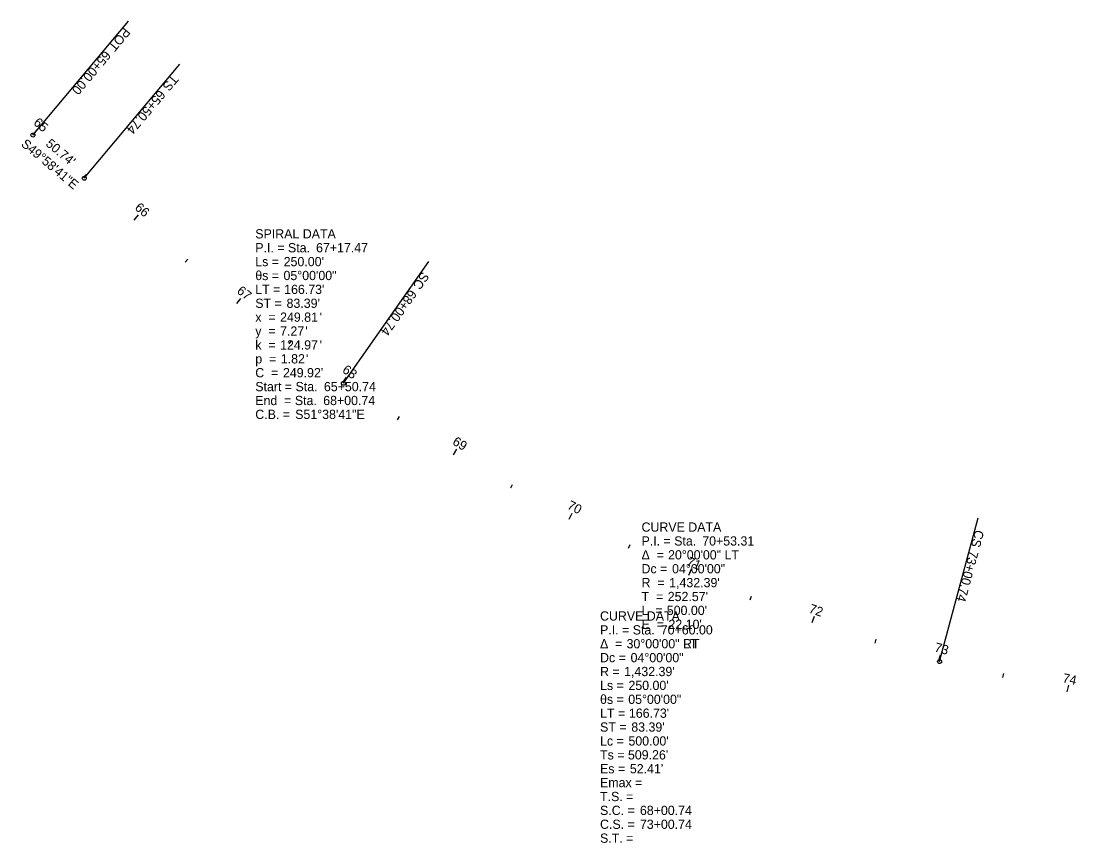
# Model space of a CAD drawing. Extents: x 1999328 to 2003366, y 252318 to 253988.
# Drawn here: x 1999328 to 2000126, y 253367 to 253988 of the extents above; entities that cross this region are included whole.
import ezdxf

# ---------------------------------------------------------------- set-up
doc = ezdxf.new("R2010")
doc.units = 0
for name, color, linetype in [('GE_P_Alignment_500_Stations', 7, 'Continuous'), ('GE_X_Alignment_100_Stations', 7, 'Continuous'), ('SC_Scratch3', 7, 'Continuous'), ('SV_X_Mon_Cells_Found', 7, 'Continuous'), ('TX_P_50', 7, 'Continuous'), ('TX_X_50', 7, 'Continuous')]:
    doc.layers.add(name, color=color, linetype=linetype)

msp = doc.modelspace()

# ---------------------------------------------------------------- linework, layer by layer
at = {"layer": 'GE_P_Alignment_500_Stations'}
for p, q in [((1999336.91, 253901.92), (1999409.26, 253988.07)), ((1999375.77, 253869.29), (1999448.11, 253955.44)), ((1999336.91, 253901.92), (1999340.13, 253905.75)), ((1999375.2, 253869.77), (1999377.13, 253872.07)), ((1999413.53, 253837.66), (1999416.73, 253841.5)), ((1999452.07, 253805.81), (1999453.97, 253808.13)), ((1999571.75, 253714.21), (1999636.31, 253806.34)), ((1999491.06, 253774.5), (1999494.15, 253778.43)), ((1999530.68, 253744.01), (1999532.48, 253746.41)), ((1999571.14, 253714.63), (1999574.01, 253718.73)), ((1999612.56, 253686.64), (1999614.2, 253689.15)), ((1999654.94, 253660.11), (1999657.52, 253664.39)), ((1999698.22, 253635.07), (1999699.67, 253637.69)), ((1999742.34, 253611.56), (1999744.62, 253616.01)), ((2000022.52, 253503.8), (2000051.68, 253612.46)), ((1999787.26, 253589.6), (1999788.53, 253592.32)), ((1999832.92, 253569.22), (1999834.87, 253573.82)), ((1999879.26, 253550.45), (1999880.33, 253553.25)), ((1999926.22, 253533.31), (1999927.85, 253538.04)), ((1999973.76, 253517.82), (1999974.64, 253520.68)), ((2000021.81, 253503.99), (2000023.11, 253508.82)), ((2000070.3, 253491.8), (2000070.98, 253494.72)), ((2000119.11, 253480.97), (2000120.13, 253485.86))]:
    msp.add_line(p, q, dxfattribs=at)
for centre in [(1999336.91, 253901.92), (1999375.77, 253869.29), (1999571.75, 253714.21), (2000022.52, 253503.8)]:
    msp.add_circle(centre, 1.5, dxfattribs=at)
at = {"layer": 'SV_X_Mon_Cells_Found'}
for p, q in [((1999336.91, 253901.92), (1999409.26, 253988.07)), ((1999375.77, 253869.29), (1999448.11, 253955.44)), ((1999336.91, 253901.92), (1999338.84, 253904.22)), ((1999571.75, 253714.21), (1999636.31, 253806.34)), ((1999742.34, 253611.56), (1999744.62, 253616.01)), ((2000022.52, 253503.8), (2000051.68, 253612.46))]:
    msp.add_line(p, q, dxfattribs=at)
for centre in [(1999336.91, 253901.92), (1999375.77, 253869.29), (1999571.75, 253714.21), (2000022.52, 253503.8)]:
    msp.add_circle(centre, 1.5, dxfattribs=at)
at = {"layer": 'TX_P_50'}
for p, q in [((1999336.91, 253901.92), (1999409.26, 253988.07)), ((1999375.77, 253869.29), (1999448.11, 253955.44)), ((1999336.91, 253901.92), (1999340.13, 253905.75)), ((1999413.53, 253837.66), (1999415.45, 253839.96)), ((1999571.75, 253714.21), (1999636.31, 253806.34)), ((1999491.06, 253774.5), (1999492.91, 253776.86)), ((1999571.14, 253714.63), (1999572.86, 253717.09)), ((1999654.94, 253660.11), (1999656.49, 253662.68)), ((1999742.34, 253611.56), (1999744.62, 253616.01)), ((2000022.52, 253503.8), (2000051.68, 253612.46)), ((1999832.92, 253569.22), (1999834.09, 253571.98)), ((1999926.22, 253533.31), (1999927.2, 253536.14)), ((2000021.81, 253503.99), (2000022.59, 253506.89)), ((2000119.11, 253480.97), (2000119.72, 253483.91))]:
    msp.add_line(p, q, dxfattribs=at)
for centre in [(1999336.91, 253901.92), (1999375.77, 253869.29), (1999571.75, 253714.21), (2000022.52, 253503.8)]:
    msp.add_circle(centre, 1.5, dxfattribs=at)

# ---------------------------------------------------------------- texts
at = {"layer": 'GE_P_Alignment_500_Stations'}
for s, rotation, p in [('POT', 229.97809, (1999405.8, 253983.77)), ('65+00.00', 229.97809, (1999391.12, 253966.29)), ('TS', 229.97809, (1999442.14, 253948.15)), ('65+50.74', 229.97809, (1999432.36, 253936.5)), ('65', 319.97809, (1999336.78, 253910.35)), ('S49°58\'41"E', 319.97809, (1999327.42, 253894.22)), ("50.74'", 319.97809, (1999346.08, 253894.38)), ('66', 320.17222, (1999413.39, 253846.06)), ('SC', 234.97811, (1999631.31, 253799)), ('67', 321.76038, (1999490.58, 253782.99)), ('68+00.74', 234.97811, (1999621.95, 253785.64)), ('68', 324.94855, (1999570.31, 253722.99)), ('69', 328.94852, (1999653.59, 253668.35)), ('70', 332.94853, (1999740.36, 253619.72)), ('CS', 254.97808, (2000049.49, 253603.85)), ('71', 336.94855, (1999830.71, 253576.96)), ('73+00.74', 254.97808, (2000045.26, 253588.1)), ('72', 340.94856, (1999923.1, 253541)), ('73', 344.94857, (2000018.21, 253511.55)), ('74', 348.16034, (2000115.13, 253488.19))]:
    msp.add_text(s, height=7, rotation=rotation, dxfattribs=at).set_placement(p)
at = {"layer": 'GE_X_Alignment_100_Stations'}
for s, p in [('SPIRAL DATA', (1999505.07, 253823.73)), ('P.I. = Sta. ', (1999505.07, 253813.23)), ('67+17.47', (1999550.99, 253813.23)), ('Ls = ', (1999505.07, 253802.73)), ("250.00'", (1999526.54, 253802.73)), ('θs = ', (1999505.07, 253792.23)), ('05°00\'00"', (1999526.4, 253792.23)), ('LT = ', (1999505.07, 253781.73)), ("166.73'", (1999526.89, 253781.73)), ('ST = ', (1999505.07, 253771.23)), ("83.39'", (1999528.71, 253771.23)), ('x  = ', (1999505.07, 253760.73)), ('249.81', (1999523.82, 253760.73)), ("'", (1999553.72, 253760.73)), ('7.27', (1999523.82, 253750.23)), ("'", (1999542.84, 253750.23)), ('y  = ', (1999505.07, 253750.23)), ('k  = ', (1999505.07, 253739.73)), ('124.97', (1999523.82, 253739.73)), ("'", (1999553.72, 253739.73)), ('p  = ', (1999505.07, 253729.23)), ('1.82', (1999524.36, 253729.23)), ("'", (1999543.39, 253729.23)), ('C  = ', (1999505.07, 253718.73)), ("249.92'", (1999525.99, 253718.73)), ('Start = Sta. ', (1999505.07, 253708.23)), ('65+50.74', (1999556.96, 253708.23)), ('End  = Sta. ', (1999505.07, 253697.73)), ('68+00.74', (1999556.43, 253697.73)), ('C.B. = ', (1999505.07, 253687.23)), ('S51°38\'41"E', (1999535.23, 253687.23)), ('CURVE DATA', (1999797.13, 253602.01)), ('P.I. = Sta. ', (1999797.13, 253591.51)), ('70+53.31', (1999843.05, 253591.51)), ('Δ  = ', (1999797.13, 253581.01)), ('20°00\'00" LT', (1999817.19, 253581.01)), ('Dc = ', (1999797.13, 253570.51)), ('04°00\'00"', (1999820.23, 253570.51)), ('R  = ', (1999797.13, 253560.01)), ("1,432.39'", (1999818.05, 253560.01)), ('T  = ', (1999797.13, 253549.51)), ("252.57'", (1999816.96, 253549.51)), ('CURVE DATA', (1999765.76, 253534.79)), ('CURVE DATA', (1999765.76, 253534.79)), ('L  = ', (1999797.13, 253539.01)), ("500.00'", (1999816.25, 253539.01)), ('E  = ', (1999797.13, 253528.51)), ("22.10'", (1999817.51, 253528.51)), ('P.I. = Sta. ', (1999765.76, 253524.29)), ('P.I. = Sta. ', (1999765.76, 253524.29)), ('70+60.00', (1999811.68, 253524.29)), ('70+60.00', (1999811.68, 253524.29)), ('Δ  = ', (1999765.76, 253513.79)), ('Δ  = ', (1999765.76, 253513.79)), ('30°00\'00" LT', (1999785.82, 253513.79)), ('30°00\'00" RT', (1999785.82, 253513.79)), ('Dc = ', (1999765.76, 253503.29)), ('Dc = ', (1999765.76, 253503.29)), ('04°00\'00"', (1999788.86, 253503.29)), ('04°00\'00"', (1999788.86, 253503.29)), ('R = ', (1999765.76, 253492.79)), ('R = ', (1999765.76, 253492.79)), ("1,432.39'", (1999783.97, 253492.79)), ("1,432.39'", (1999783.97, 253492.79)), ('Ls = ', (1999765.76, 253482.29)), ('Ls = ', (1999765.76, 253482.29)), ("250.00'", (1999787.23, 253482.29)), ("250.00'", (1999787.23, 253482.29)), ('θs = ', (1999765.76, 253471.79)), ('θs = ', (1999765.76, 253471.79)), ('05°00\'00"', (1999787.1, 253471.79)), ('05°00\'00"', (1999787.1, 253471.79)), ('LT = ', (1999765.76, 253461.29)), ('LT = ', (1999765.76, 253461.29)), ("166.73'", (1999787.59, 253461.29)), ("166.73'", (1999787.59, 253461.29)), ('ST = ', (1999765.76, 253450.79)), ('ST = ', (1999765.76, 253450.79)), ("83.39'", (1999789.4, 253450.79)), ("83.39'", (1999789.4, 253450.79)), ('Lc = ', (1999765.76, 253440.29)), ('Lc = ', (1999765.76, 253440.29)), ("500.00'", (1999787.23, 253440.29)), ("500.00'", (1999787.23, 253440.29)), ('Ts = ', (1999765.76, 253429.79)), ('Ts = ', (1999765.76, 253429.79)), ("509.26'", (1999786.87, 253429.79)), ("509.26'", (1999786.87, 253429.79)), ('Es = ', (1999765.76, 253419.29)), ('Es = ', (1999765.76, 253419.29)), ("52.41'", (1999788.32, 253419.29)), ("52.41'", (1999788.32, 253419.29)), ('Emax = ', (1999765.76, 253408.79)), ('Emax = ', (1999765.76, 253408.79)), ('T.S. = ', (1999765.76, 253398.29)), ('T.S. = ', (1999765.76, 253398.29)), ('S.C. = ', (1999765.76, 253387.79)), ('S.C. = ', (1999765.76, 253387.79)), ('68+00.74', (1999795.92, 253387.79)), ('68+00.74', (1999795.92, 253387.79)), ('C.S. = ', (1999765.76, 253377.29)), ('C.S. = ', (1999765.76, 253377.29)), ('73+00.74', (1999795.92, 253377.29)), ('73+00.74', (1999795.92, 253377.29)), ('S.T. = ', (1999765.76, 253366.79)), ('S.T. = ', (1999765.76, 253366.79))]:
    msp.add_text(s, height=7, dxfattribs=at).set_placement(p)
at = {"layer": 'SC_Scratch3'}
for s, p in [('SPIRAL DATA', (1999505.07, 253823.73)), ('P.I. = Sta. ', (1999505.07, 253813.23)), ('67+17.47', (1999550.99, 253813.23)), ('Ls = ', (1999505.07, 253802.73)), ("250.00'", (1999526.54, 253802.73)), ('θs = ', (1999505.07, 253792.23)), ('05°00\'00"', (1999526.4, 253792.23)), ('LT = ', (1999505.07, 253781.73)), ("166.73'", (1999526.89, 253781.73)), ('ST = ', (1999505.07, 253771.23)), ("83.39'", (1999528.71, 253771.23)), ('x  = ', (1999505.07, 253760.73)), ('249.81', (1999523.82, 253760.73)), ("'", (1999553.72, 253760.73)), ('7.27', (1999523.82, 253750.23)), ("'", (1999542.84, 253750.23)), ('y  = ', (1999505.07, 253750.23)), ('k  = ', (1999505.07, 253739.73)), ('124.97', (1999523.82, 253739.73)), ("'", (1999553.72, 253739.73)), ('p  = ', (1999505.07, 253729.23)), ('1.82', (1999524.36, 253729.23)), ("'", (1999543.39, 253729.23)), ('C  = ', (1999505.07, 253718.73)), ("249.92'", (1999525.99, 253718.73)), ('Start = Sta. ', (1999505.07, 253708.23)), ('65+50.74', (1999556.96, 253708.23)), ('End  = Sta. ', (1999505.07, 253697.73)), ('68+00.74', (1999556.43, 253697.73)), ('C.B. = ', (1999505.07, 253687.23)), ('S51°38\'41"E', (1999535.23, 253687.23)), ('CURVE DATA', (1999797.13, 253602.01)), ('P.I. = Sta. ', (1999797.13, 253591.51)), ('70+53.31', (1999843.05, 253591.51)), ('Δ  = ', (1999797.13, 253581.01)), ('20°00\'00" LT', (1999817.19, 253581.01)), ('Dc = ', (1999797.13, 253570.51)), ('04°00\'00"', (1999820.23, 253570.51)), ('R  = ', (1999797.13, 253560.01)), ("1,432.39'", (1999818.05, 253560.01)), ('T  = ', (1999797.13, 253549.51)), ("252.57'", (1999816.96, 253549.51)), ('CURVE DATA', (1999765.76, 253534.79)), ('CURVE DATA', (1999765.76, 253534.79)), ('L  = ', (1999797.13, 253539.01)), ("500.00'", (1999816.25, 253539.01)), ('E  = ', (1999797.13, 253528.51)), ("22.10'", (1999817.51, 253528.51)), ('P.I. = Sta. ', (1999765.76, 253524.29)), ('P.I. = Sta. ', (1999765.76, 253524.29)), ('70+60.00', (1999811.68, 253524.29)), ('70+60.00', (1999811.68, 253524.29)), ('Δ  = ', (1999765.76, 253513.79)), ('Δ  = ', (1999765.76, 253513.79)), ('30°00\'00" LT', (1999785.82, 253513.79)), ('30°00\'00" RT', (1999785.82, 253513.79)), ('Dc = ', (1999765.76, 253503.29)), ('Dc = ', (1999765.76, 253503.29)), ('04°00\'00"', (1999788.86, 253503.29)), ('04°00\'00"', (1999788.86, 253503.29)), ('R = ', (1999765.76, 253492.79)), ('R = ', (1999765.76, 253492.79)), ("1,432.39'", (1999783.97, 253492.79)), ("1,432.39'", (1999783.97, 253492.79)), ('Ls = ', (1999765.76, 253482.29)), ('Ls = ', (1999765.76, 253482.29)), ("250.00'", (1999787.23, 253482.29)), ("250.00'", (1999787.23, 253482.29)), ('θs = ', (1999765.76, 253471.79)), ('θs = ', (1999765.76, 253471.79)), ('05°00\'00"', (1999787.1, 253471.79)), ('05°00\'00"', (1999787.1, 253471.79)), ('LT = ', (1999765.76, 253461.29)), ('LT = ', (1999765.76, 253461.29)), ("166.73'", (1999787.59, 253461.29)), ("166.73'", (1999787.59, 253461.29)), ('ST = ', (1999765.76, 253450.79)), ('ST = ', (1999765.76, 253450.79)), ("83.39'", (1999789.4, 253450.79)), ("83.39'", (1999789.4, 253450.79)), ('Lc = ', (1999765.76, 253440.29)), ('Lc = ', (1999765.76, 253440.29)), ("500.00'", (1999787.23, 253440.29)), ("500.00'", (1999787.23, 253440.29)), ('Ts = ', (1999765.76, 253429.79)), ('Ts = ', (1999765.76, 253429.79)), ("509.26'", (1999786.87, 253429.79)), ("509.26'", (1999786.87, 253429.79)), ('Es = ', (1999765.76, 253419.29)), ('Es = ', (1999765.76, 253419.29)), ("52.41'", (1999788.32, 253419.29)), ("52.41'", (1999788.32, 253419.29)), ('Emax = ', (1999765.76, 253408.79)), ('Emax = ', (1999765.76, 253408.79)), ('T.S. = ', (1999765.76, 253398.29)), ('T.S. = ', (1999765.76, 253398.29)), ('S.C. = ', (1999765.76, 253387.79)), ('S.C. = ', (1999765.76, 253387.79)), ('68+00.74', (1999795.92, 253387.79)), ('68+00.74', (1999795.92, 253387.79)), ('C.S. = ', (1999765.76, 253377.29)), ('C.S. = ', (1999765.76, 253377.29)), ('73+00.74', (1999795.92, 253377.29)), ('73+00.74', (1999795.92, 253377.29)), ('S.T. = ', (1999765.76, 253366.79)), ('S.T. = ', (1999765.76, 253366.79))]:
    msp.add_text(s, height=7, dxfattribs=at).set_placement(p)
at = {"layer": 'SV_X_Mon_Cells_Found'}
for s, rotation, p in [('POT', 229.97809, (1999405.8, 253983.77)), ('65+00.00', 229.97809, (1999391.12, 253966.29)), ('TS', 229.97809, (1999442.14, 253948.15)), ('65+50.74', 229.97809, (1999432.36, 253936.5)), ('S49°58\'41"E', 319.97809, (1999327.42, 253894.22)), ("50.74'", 319.97809, (1999346.08, 253894.38)), ('SC', 234.97811, (1999631.31, 253799)), ('68+00.74', 234.97811, (1999621.95, 253785.64)), ('70', 332.94853, (1999740.36, 253619.72)), ('CS', 254.97808, (2000049.49, 253603.85)), ('73+00.74', 254.97808, (2000045.26, 253588.1))]:
    msp.add_text(s, height=7, rotation=rotation, dxfattribs=at).set_placement(p)
at = {"layer": 'TX_P_50'}
for s, rotation, p in [('POT', 229.97809, (1999405.8, 253983.77)), ('65+00.00', 229.97809, (1999391.12, 253966.29)), ('TS', 229.97809, (1999442.14, 253948.15)), ('65+50.74', 229.97809, (1999432.36, 253936.5)), ('65', 319.97809, (1999336.78, 253910.35)), ('S49°58\'41"E', 319.97809, (1999327.42, 253894.22)), ("50.74'", 319.97809, (1999346.08, 253894.38)), ('SC', 234.97811, (1999631.31, 253799)), ('68+00.74', 234.97811, (1999621.95, 253785.64)), ('70', 332.94853, (1999740.36, 253619.72)), ('CS', 254.97808, (2000049.49, 253603.85)), ('73+00.74', 254.97808, (2000045.26, 253588.1))]:
    msp.add_text(s, height=7, rotation=rotation, dxfattribs=at).set_placement(p)
at = {"layer": 'TX_X_50'}
for s, p in [('SPIRAL DATA', (1999505.07, 253823.73)), ('P.I. = Sta. ', (1999505.07, 253813.23)), ('67+17.47', (1999550.99, 253813.23)), ('Ls = ', (1999505.07, 253802.73)), ("250.00'", (1999526.54, 253802.73)), ('θs = ', (1999505.07, 253792.23)), ('05°00\'00"', (1999526.4, 253792.23)), ('LT = ', (1999505.07, 253781.73)), ("166.73'", (1999526.89, 253781.73)), ('ST = ', (1999505.07, 253771.23)), ("83.39'", (1999528.71, 253771.23)), ('x  = ', (1999505.07, 253760.73)), ('249.81', (1999523.82, 253760.73)), ("'", (1999553.72, 253760.73)), ('7.27', (1999523.82, 253750.23)), ("'", (1999542.84, 253750.23)), ('y  = ', (1999505.07, 253750.23)), ('k  = ', (1999505.07, 253739.73)), ('124.97', (1999523.82, 253739.73)), ("'", (1999553.72, 253739.73)), ('p  = ', (1999505.07, 253729.23)), ('1.82', (1999524.36, 253729.23)), ("'", (1999543.39, 253729.23)), ('C  = ', (1999505.07, 253718.73)), ("249.92'", (1999525.99, 253718.73)), ('Start = Sta. ', (1999505.07, 253708.23)), ('65+50.74', (1999556.96, 253708.23)), ('End  = Sta. ', (1999505.07, 253697.73)), ('68+00.74', (1999556.43, 253697.73)), ('C.B. = ', (1999505.07, 253687.23)), ('S51°38\'41"E', (1999535.23, 253687.23)), ('CURVE DATA', (1999797.13, 253602.01)), ('P.I. = Sta. ', (1999797.13, 253591.51)), ('70+53.31', (1999843.05, 253591.51)), ('Δ  = ', (1999797.13, 253581.01)), ('20°00\'00" LT', (1999817.19, 253581.01)), ('Dc = ', (1999797.13, 253570.51)), ('04°00\'00"', (1999820.23, 253570.51)), ('R  = ', (1999797.13, 253560.01)), ("1,432.39'", (1999818.05, 253560.01)), ('T  = ', (1999797.13, 253549.51)), ("252.57'", (1999816.96, 253549.51)), ('CURVE DATA', (1999765.76, 253534.79)), ('CURVE DATA', (1999765.76, 253534.79)), ('L  = ', (1999797.13, 253539.01)), ("500.00'", (1999816.25, 253539.01)), ('E  = ', (1999797.13, 253528.51)), ("22.10'", (1999817.51, 253528.51)), ('P.I. = Sta. ', (1999765.76, 253524.29)), ('P.I. = Sta. ', (1999765.76, 253524.29)), ('70+60.00', (1999811.68, 253524.29)), ('70+60.00', (1999811.68, 253524.29)), ('Δ  = ', (1999765.76, 253513.79)), ('Δ  = ', (1999765.76, 253513.79)), ('30°00\'00" LT', (1999785.82, 253513.79)), ('30°00\'00" RT', (1999785.82, 253513.79)), ('Dc = ', (1999765.76, 253503.29)), ('Dc = ', (1999765.76, 253503.29)), ('04°00\'00"', (1999788.86, 253503.29)), ('04°00\'00"', (1999788.86, 253503.29)), ('R = ', (1999765.76, 253492.79)), ('R = ', (1999765.76, 253492.79)), ("1,432.39'", (1999783.97, 253492.79)), ("1,432.39'", (1999783.97, 253492.79)), ('Ls = ', (1999765.76, 253482.29)), ('Ls = ', (1999765.76, 253482.29)), ("250.00'", (1999787.23, 253482.29)), ("250.00'", (1999787.23, 253482.29)), ('θs = ', (1999765.76, 253471.79)), ('θs = ', (1999765.76, 253471.79)), ('05°00\'00"', (1999787.1, 253471.79)), ('05°00\'00"', (1999787.1, 253471.79)), ('LT = ', (1999765.76, 253461.29)), ('LT = ', (1999765.76, 253461.29)), ("166.73'", (1999787.59, 253461.29)), ("166.73'", (1999787.59, 253461.29)), ('ST = ', (1999765.76, 253450.79)), ('ST = ', (1999765.76, 253450.79)), ("83.39'", (1999789.4, 253450.79)), ("83.39'", (1999789.4, 253450.79)), ('Lc = ', (1999765.76, 253440.29)), ('Lc = ', (1999765.76, 253440.29)), ("500.00'", (1999787.23, 253440.29)), ("500.00'", (1999787.23, 253440.29)), ('Ts = ', (1999765.76, 253429.79)), ('Ts = ', (1999765.76, 253429.79)), ("509.26'", (1999786.87, 253429.79)), ("509.26'", (1999786.87, 253429.79)), ('Es = ', (1999765.76, 253419.29)), ('Es = ', (1999765.76, 253419.29)), ("52.41'", (1999788.32, 253419.29)), ("52.41'", (1999788.32, 253419.29)), ('Emax = ', (1999765.76, 253408.79)), ('Emax = ', (1999765.76, 253408.79)), ('T.S. = ', (1999765.76, 253398.29)), ('T.S. = ', (1999765.76, 253398.29)), ('S.C. = ', (1999765.76, 253387.79)), ('S.C. = ', (1999765.76, 253387.79)), ('68+00.74', (1999795.92, 253387.79)), ('68+00.74', (1999795.92, 253387.79)), ('C.S. = ', (1999765.76, 253377.29)), ('C.S. = ', (1999765.76, 253377.29)), ('73+00.74', (1999795.92, 253377.29)), ('73+00.74', (1999795.92, 253377.29)), ('S.T. = ', (1999765.76, 253366.79)), ('S.T. = ', (1999765.76, 253366.79))]:
    msp.add_text(s, height=7, dxfattribs=at).set_placement(p)

doc.saveas('drawing.dxf')
